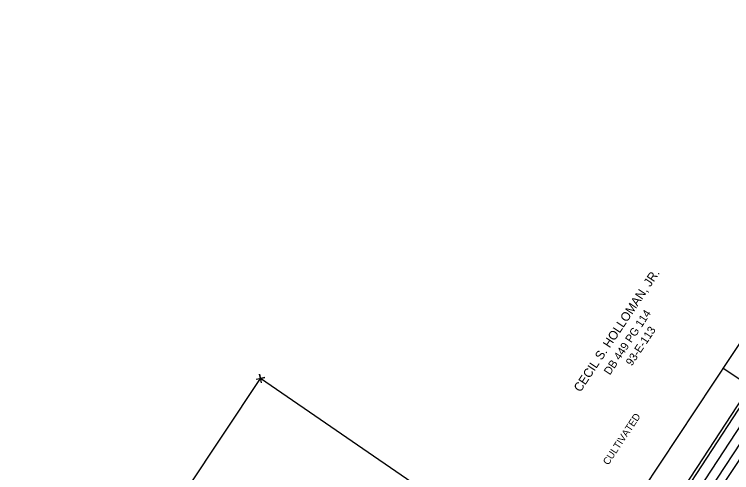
# Model space of a CAD drawing. Extents: x 2603627 to 2605187, y 896619 to 899063.
# Drawn here: x 2604469.2 to 2604872.4, y 898681.8 to 898939.4 of the extents above; entities that cross this region are included whole.
import ezdxf

# ---------------------------------------------------------------- set-up
doc = ezdxf.new("R2010")
doc.units = 0
for name, color, linetype in [('Exist Other Culture Area Outline Text', 7, 'Continuous'), ('Exist Property Corner CELL', 7, 'Continuous'), ('Exist Property Deed Book Text', 7, 'Continuous'), ('Exist Property Line', 7, 'Continuous'), ('Exist Property Owner Text', 7, 'Continuous'), ('Exist Right of Way Line', 7, 'Continuous'), ('Exist Right of Way Width CELL', 7, 'Continuous'), ('Exist Roads EOP', 7, 'Continuous'), ('Exist Utilities Telephone UG Cable SUE LOS C', 7, 'Continuous'), ('Exist Utilities Telephone UG FO SUE LOS C', 7, 'Continuous')]:
    doc.layers.add(name, color=color, linetype=linetype)

msp = doc.modelspace()

# ---------------------------------------------------------------- linework, layer by layer
at = {"layer": 'Exist Property Corner CELL'}
msp.add_line((2604607.56, 898734.76), (2604607.56, 898734.76), dxfattribs=at)
msp.add_lwpolyline([(2604605.1, 898734.31), (2604610.02, 898735.22), (2604607.56, 898734.76), (2604607.1, 898737.22), (2604608.01, 898732.31)], dxfattribs=at)
at = {"layer": 'Exist Property Line'}
for p in [(2604469.25, 898526.47), (2604783.72, 898613.72)]:
    msp.add_line(p, (2604607.56, 898734.76), dxfattribs=at)
at = {"layer": 'Exist Right of Way Line'}
msp.add_line((2604639.76, 898396.41), (2604999.42, 898939.36), dxfattribs=at)
at = {"layer": 'Exist Right of Way Width CELL'}
msp.add_line((2604867.64, 898740.42), (2604938.61, 898693.4), dxfattribs=at)
at = {"layer": 'Exist Roads EOP'}
msp.add_lwpolyline([(2604577.96, 898237.27), (2604606.45, 898281.24), (2604633.89, 898322.5), (2604662.45, 898365.47), (2604690.62, 898408.06), (2604717.29, 898448.09), (2604745.46, 898490.11), (2604773.6, 898532.6), (2604800.88, 898573.95), (2604828.34, 898615.46), (2604855.1, 898656.15), (2604883.53, 898699.09), (2604911.29, 898740.95), (2604939.38, 898783.41), (2604966.33, 898824.04), (2604993.38, 898865.27), (2605022.2, 898908.38), (2605029.46, 898919.46)], dxfattribs=at)
at = {"layer": 'Exist Utilities Telephone UG Cable SUE LOS C'}
for p, q in [((2604852.96, 898684.66), (2605013.55, 898930.01)), ((2604797.03, 898576.37), (2605024.91, 898922.48)), ((2604658.71, 898389.49), (2604852.96, 898684.66))]:
    msp.add_line(p, q, dxfattribs=at)
at = {"layer": 'Exist Utilities Telephone UG FO SUE LOS C'}
for p, q in [((2604671.2, 898402.26), (2605014.35, 898929.48)), ((2604676.14, 898398.98), (2605019.3, 898926.2))]:
    msp.add_line(p, q, dxfattribs=at)

# ---------------------------------------------------------------- texts
at = {"layer": 'Exist Other Culture Area Outline Text'}
msp.add_text('CULTIVATED', height=4, rotation=56.4786, dxfattribs=at).set_placement((2604803.05, 898685.72))
at = {"layer": 'Exist Property Deed Book Text'}
for s, p in [('DB 449 PG 114', (2604803.98, 898736.31)), ('93-E-113', (2604816.3, 898741.44))]:
    msp.add_text(s, height=4.5, rotation=56.4133, dxfattribs=at).set_placement(p)
at = {"layer": 'Exist Property Owner Text'}
msp.add_text('CECIL S. HOLLOMAN, JR.', height=5, rotation=56.4133, dxfattribs=at).set_placement((2604787.43, 898726.7))

doc.saveas('drawing.dxf')
